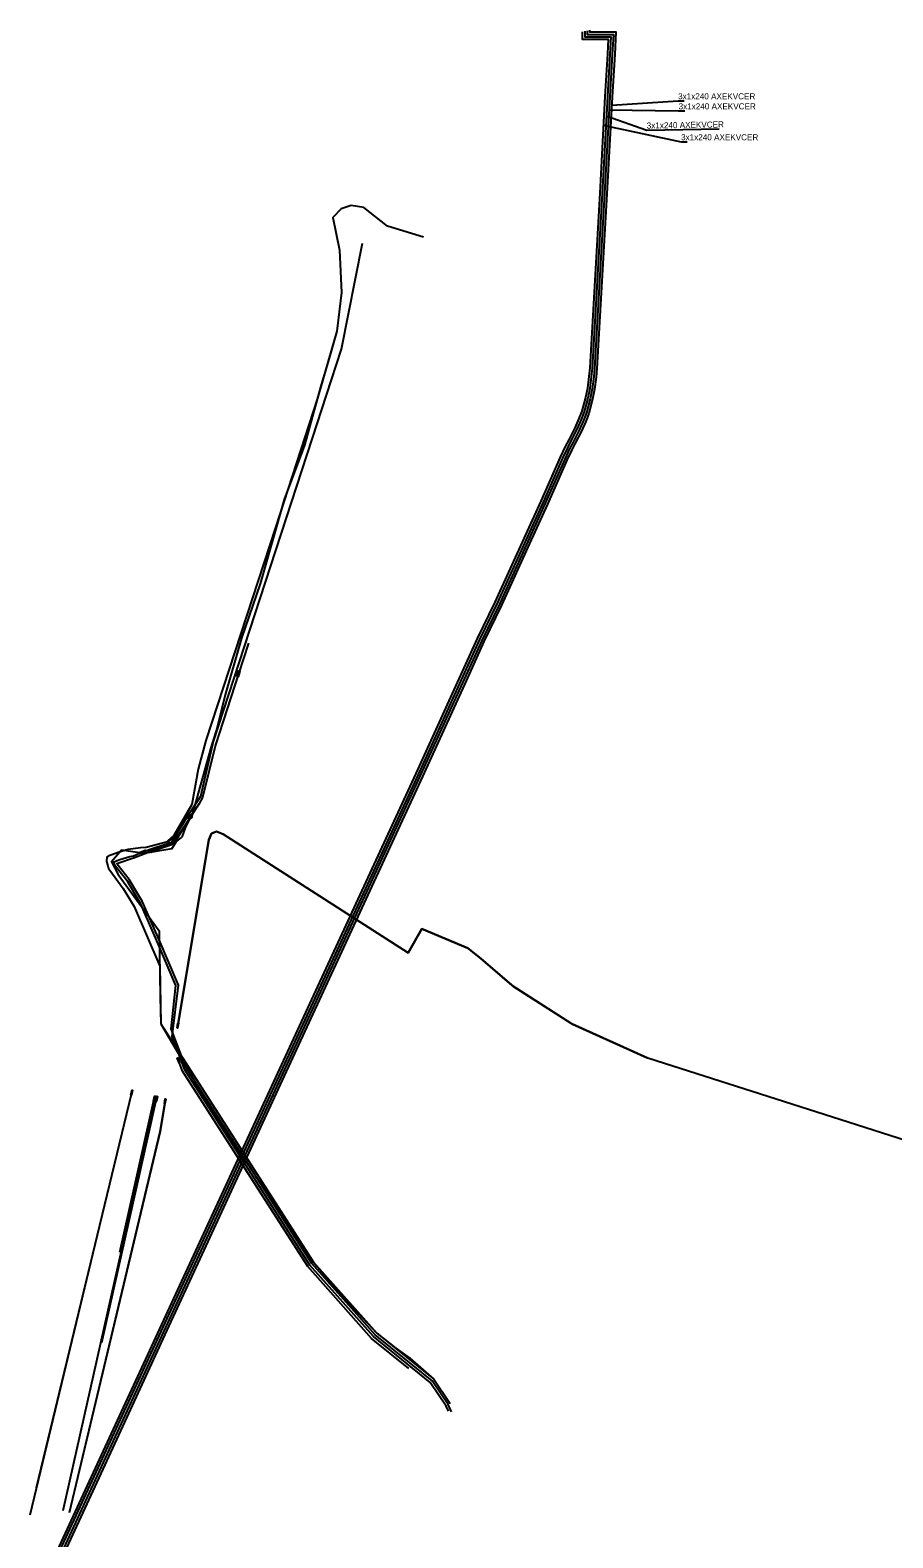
# Model space of a CAD drawing. Extents: x -739895 to -737975, y -1046419 to -1045728.
# Drawn here: x -739198.8 to -739056.8, y -1046188.1 to -1045939.9 of the extents above; entities that cross this region are included whole.
import ezdxf

# ---------------------------------------------------------------- set-up
doc = ezdxf.new("R2010")
doc.units = 0
for name, color, linetype in [('TRASA_KABELU_VN_VYRAZENO', 7, 'Continuous'), ('VN_KABEL_TUNEL_PROVOZ', 7, 'Continuous'), ('VN_KABELOVE_VEDENI_VYRAZENO', 7, 'Continuous'), ('VN_POPIS_USEKU', 7, 'Continuous'), ('VN_SPOJKA_KONCOVKA', 7, 'Continuous')]:
    doc.layers.add(name, color=color, linetype=linetype)

msp = doc.modelspace()

# ---------------------------------------------------------------- linework, layer by layer
at = {"layer": 'TRASA_KABELU_VN_VYRAZENO'}
msp.add_line((-739178.21, -1046115.97), (-739193.43, -1046183.61), dxfattribs=at)
for points in [[(-739148.32, -1045989.43), (-739149.62, -1045994.05), (-739150.99, -1045998.68), (-739153.66, -1046008.21), (-739156.99, -1046017.12), (-739160.95, -1046031.02), (-739164.01, -1046039.99), (-739166.72, -1046049.28), (-739168.02, -1046054.67), (-739169.05, -1046058.01), (-739172.05, -1046068.83), (-739173.23, -1046071.03), (-739173.85, -1046072.72)], [(-739179.85, -1046075.35), (-739178.93, -1046075.07), (-739176.29, -1046074.22), (-739175.36, -1046073.87), (-739174.34, -1046072.48), (-739172.35, -1046069.32), (-739172.05, -1046068.83)], [(-738876.38, -1046179.23), (-739024.54, -1046132.29), (-739066.73, -1046118.79), (-739097.09, -1046109.08), (-739109.65, -1046103.44), (-739119.45, -1046097.15), (-739124.59, -1046092.72), (-739126.74, -1046090.97), (-739134.31, -1046087.79), (-739136.59, -1046091.75), (-739167.03, -1046072.24), (-739168.14, -1046071.79), (-739168.96, -1046072.13), (-739169.37, -1046073.14), (-739174.49, -1046103.7)], [(-739175.5, -1046074.65), (-739174.74, -1046073.5), (-739173.85, -1046072.72)], [(-739175.5, -1046074.65), (-739180.04, -1046075.39), (-739183.77, -1046074.88), (-739185.43, -1046076.8), (-739184.29, -1046078.86), (-739177.54, -1046088.16), (-739177.39, -1046099.03), (-739177.26, -1046103.47), (-739174.03, -1046108.96)], [(-739174.03, -1046108.96), (-739169.11, -1046117.32), (-739152.13, -1046142.68), (-739146.27, -1046149.48), (-739141.75, -1046154.34), (-739138.61, -1046156.83), (-739136.28, -1046158.45), (-739132.33, -1046161.95)], [(-739198.8, -1046184.27), (-739187.7, -1046138.17), (-739182.07, -1046114.82)], [(-739192.34, -1046183.86), (-739177.42, -1046121.18), (-739176.59, -1046116.25)]]:
    msp.add_lwpolyline(points, dxfattribs=at)
at = {"layer": 'VN_KABEL_TUNEL_PROVOZ'}
for points in [[(-739107.92, -1045940.16), (-739107.91, -1045941.39), (-739103.63, -1045941.39), (-739103.76, -1045943.81), (-739104.18, -1045950.79), (-739105.04, -1045966.74), (-739106.69, -1045995.5), (-739106.82, -1045996.89), (-739107.05, -1045998.81), (-739107.38, -1046000.36), (-739107.99, -1046002.61), (-739108.45, -1046003.83), (-739109.14, -1046005.37), (-739110.14, -1046007.32), (-739110.71, -1046008.44), (-739111.53, -1046010.16), (-739114.74, -1046017.44), (-739122.29, -1046034.03), (-739125.19, -1046040.01), (-739135.31, -1046062.26), (-739198.32, -1046198.69)], [(-739107.51, -1045940.07), (-739107.51, -1045940.99), (-739103.21, -1045940.99), (-739103.36, -1045943.84), (-739103.78, -1045950.82), (-739104.65, -1045966.76), (-739106.29, -1045995.53), (-739106.42, -1045996.93), (-739106.66, -1045998.88), (-739106.99, -1046000.45), (-739107.61, -1046002.73), (-739108.08, -1046003.98), (-739108.78, -1046005.55), (-739109.79, -1046007.51), (-739110.35, -1046008.62), (-739111.16, -1046010.32), (-739114.37, -1046017.6), (-739121.92, -1046034.2), (-739124.82, -1046040.18), (-739134.94, -1046062.43), (-739197.96, -1046198.87)], [(-739107.11, -1045939.98), (-739107.11, -1045940.59), (-739102.79, -1045940.59), (-739102.96, -1045943.86), (-739103.38, -1045950.84), (-739104.24, -1045966.79), (-739105.89, -1045995.56), (-739106.03, -1045996.97), (-739106.26, -1045998.95), (-739106.6, -1046000.55), (-739107.23, -1046002.86), (-739107.71, -1046004.14), (-739108.42, -1046005.72), (-739109.43, -1046007.69), (-739110, -1046008.79), (-739110.8, -1046010.49), (-739114.01, -1046017.77), (-739121.56, -1046034.37), (-739124.46, -1046040.35), (-739134.58, -1046062.59), (-739197.61, -1046199.05)], [(-739106.71, -1045939.89), (-739106.71, -1045940.19), (-739102.36, -1045940.19), (-739102.56, -1045943.88), (-739102.98, -1045950.86), (-739103.85, -1045966.81), (-739105.49, -1045995.59), (-739105.63, -1045997.02), (-739105.87, -1045999.01), (-739106.21, -1046000.64), (-739106.85, -1046002.98), (-739107.34, -1046004.29), (-739108.06, -1046005.89), (-739109.07, -1046007.87), (-739109.64, -1046008.97), (-739110.44, -1046010.66), (-739113.64, -1046017.93), (-739116.58, -1046024.4), (-739121.2, -1046034.54), (-739124.1, -1046040.52), (-739127.03, -1046046.97), (-739134.21, -1046062.76), (-739139.84, -1046074.95), (-739143.87, -1046083.66), (-739150.56, -1046098.15), (-739157.62, -1046113.44), (-739162.78, -1046124.6), (-739170.22, -1046140.72), (-739176.62, -1046154.56), (-739182.96, -1046168.29), (-739189.49, -1046182.43), (-739195.85, -1046196.21)]]:
    msp.add_lwpolyline(points, dxfattribs=at)
at = {"layer": 'VN_KABELOVE_VEDENI_VYRAZENO'}
for p, q in [((-739162.84, -1046040.77), (-739164.52, -1046045.83)), ((-739186.98, -1046155.87), (-739177.98, -1046115.81)), ((-739184.06, -1046141.03), (-739178.38, -1046115.78))]:
    msp.add_line(p, q, dxfattribs=at)
for points in [[(-739134.05, -1045973.96), (-739139.96, -1045972.13), (-739143.84, -1045969.11), (-739145.95, -1045968.78), (-739147.6, -1045969.32), (-739148.98, -1045970.73), (-739147.9, -1045976.09), (-739147.55, -1045983.05), (-739148.32, -1045989.43), (-739151.49, -1046000.47), (-739158.41, -1046021.78), (-739169.89, -1046056.8), (-739171.13, -1046061.51), (-739172.17, -1046067.37), (-739173.99, -1046070.5), (-739175.33, -1046072.71), (-739175.79, -1046073.14)], [(-739180.29, -1046075.16), (-739178.24, -1046074.45), (-739175.49, -1046073.56), (-739172.71, -1046069.04), (-739170.68, -1046065.98), (-739168.74, -1046057.42), (-739168.68, -1046057.16), (-739152.34, -1046007.07), (-739150.02, -1046000), (-739147.53, -1045992.41), (-739144.07, -1045974.97)], [(-739164.52, -1046045.83), (-739168.3, -1046057.53), (-739170.42, -1046066.21), (-739171.03, -1046067.27), (-739172.39, -1046069.37)], [(-739172.39, -1046069.37), (-739173.38, -1046070.93), (-739173.97, -1046071.87), (-739174.79, -1046073.05)], [(-739174.49, -1046103.7), (-739169.37, -1046073.14), (-739168.96, -1046072.13), (-739168.14, -1046071.79), (-739167.03, -1046072.24), (-739136.59, -1046091.75), (-739134.31, -1046087.79), (-739126.74, -1046090.97), (-739124.59, -1046092.72), (-739119.58, -1046097.05), (-739119.32, -1046097.24), (-739109.79, -1046103.35), (-739109.5, -1046103.5), (-739097.2, -1046109.03), (-739096.96, -1046109.12), (-739086.49, -1046112.47)], [(-739175.79, -1046073.14), (-739176.21, -1046073.48), (-739179.69, -1046074.41), (-739180.61, -1046074.5), (-739182.67, -1046074.73), (-739184.33, -1046075.22), (-739185.97, -1046075.85), (-739186.19, -1046076.02), (-739186.25, -1046076.72), (-739186.01, -1046077.42), (-739185.92, -1046077.9), (-739185.7, -1046078.16), (-739183.47, -1046081.17), (-739181.69, -1046084.11), (-739177.46, -1046093.98), (-739177.26, -1046103.47), (-739152.13, -1046142.68), (-739141.75, -1046154.34), (-739132.33, -1046161.95), (-739129.64, -1046165.93)], [(-739174.79, -1046073.05), (-739175.36, -1046073.88), (-739176.24, -1046074.16), (-739178.92, -1046075.02)], [(-739129.45, -1046167.31), (-739130, -1046166.1), (-739132.63, -1046162.22), (-739142.02, -1046154.64), (-739152.45, -1046142.92), (-739173.18, -1046110.58), (-739175.61, -1046104.27), (-739174.8, -1046097.16), (-739177.93, -1046089.79), (-739180.55, -1046083.77), (-739182.72, -1046080.1), (-739184.58, -1046077.74), (-739184.85, -1046077.35), (-739185.01, -1046076.8), (-739184.01, -1046076.41), (-739182.39, -1046075.89), (-739181.79, -1046075.77), (-739180.29, -1046075.16)], [(-739129.94, -1046167.2), (-739130.3, -1046166.38), (-739132.93, -1046162.49), (-739142.3, -1046154.93), (-739152.77, -1046143.17), (-739173.36, -1046111.04), (-739175.43, -1046105.54), (-739174.39, -1046097.07), (-739177.57, -1046089.61), (-739180.36, -1046083.28), (-739180.98, -1046082.25), (-739182.51, -1046079.7), (-739184.31, -1046077.39), (-739184.52, -1046077.05), (-739181.64, -1046076.09), (-739178.92, -1046075.02)], [(-739136.47, -1046160.15), (-739142.58, -1046155.22), (-739153.09, -1046143.41), (-739173.72, -1046111.23), (-739174.37, -1046109.5)], [(-739197.74, -1046179.79), (-739187.7, -1046138.17), (-739182.07, -1046114.82)], [(-739176.59, -1046116.25), (-739177.42, -1046121.18), (-739191.21, -1046179.11)]]:
    msp.add_lwpolyline(points, dxfattribs=at)
at = {"layer": 'VN_POPIS_USEKU'}
for points in [[(-739103.03, -1045952.26), (-739092.13, -1045951.53), (-739091.13, -1045951.53)], [(-739103.95, -1045953.99), (-739097.29, -1045956.35), (-739085.37, -1045956.16)], [(-739103.54, -1045952.99), (-739092.05, -1045953.18), (-739091.05, -1045953.18)], [(-739104.46, -1045955.52), (-739091.64, -1045958.27), (-739090.64, -1045958.27)]]:
    msp.add_lwpolyline(points, dxfattribs=at)
at = {"layer": 'VN_SPOJKA_KONCOVKA'}
for points in [[(-739164.76, -1046046.28), (-739164.45, -1046045.32), (-739164.27, -1046045.38), (-739164.58, -1046046.34)], [(-739175.35, -1046072.87), (-739176.1, -1046073.55), (-739176.22, -1046073.41), (-739175.47, -1046072.73)], [(-739174.43, -1046072.68), (-739174.99, -1046073.52), (-739175.15, -1046073.42), (-739174.58, -1046072.58)], [(-739180.8, -1046075.25), (-739179.85, -1046074.89), (-739179.78, -1046075.06), (-739180.73, -1046075.43)], [(-739174.38, -1046103.32), (-739174.52, -1046104.14), (-739174.61, -1046104.13), (-739174.46, -1046103.31), (-739174.43, -1046103.31), (-739174.57, -1046104.08), (-739174.54, -1046104.08), (-739174.41, -1046103.32)], [(-739174.27, -1046109.88), (-739174.57, -1046109.1), (-739174.49, -1046109.07), (-739174.19, -1046109.85), (-739174.21, -1046109.86), (-739174.49, -1046109.13), (-739174.52, -1046109.14), (-739174.24, -1046109.87)], [(-739182.2, -1046115.19), (-739182.01, -1046114.37), (-739181.93, -1046114.39), (-739182.12, -1046115.21), (-739182.15, -1046115.2), (-739181.97, -1046114.44), (-739182, -1046114.43), (-739182.17, -1046115.19)], [(-739178.51, -1046116.15), (-739178.32, -1046115.33), (-739178.24, -1046115.35), (-739178.43, -1046116.17), (-739178.45, -1046116.16), (-739178.28, -1046115.4), (-739178.3, -1046115.4), (-739178.48, -1046116.16)], [(-739178.11, -1046116.18), (-739177.92, -1046115.37), (-739177.84, -1046115.39), (-739178.02, -1046116.2), (-739178.05, -1046116.2), (-739177.88, -1046115.44), (-739177.9, -1046115.43), (-739178.08, -1046116.19)], [(-739176.7, -1046116.63), (-739176.55, -1046115.81), (-739176.47, -1046115.82), (-739176.62, -1046116.64), (-739176.64, -1046116.64), (-739176.51, -1046115.87), (-739176.54, -1046115.87), (-739176.67, -1046116.63)]]:
    msp.add_lwpolyline(points, close=True, dxfattribs=at)
for points in [[(-739172.65, -1046069.83), (-739172.6, -1046069.25), (-739172.13, -1046068.92), (-739172.18, -1046069.49), (-739172.65, -1046069.83)], [(-739179.42, -1046075.2), (-739179.01, -1046074.8), (-739178.43, -1046074.84), (-739178.84, -1046075.25), (-739179.42, -1046075.2)]]:
    msp.add_lwpolyline(points, dxfattribs=at)

# ---------------------------------------------------------------- texts
at = {"layer": 'VN_POPIS_USEKU'}
for p in [(-739092.13, -1045951.28), (-739092.05, -1045952.93), (-739091.64, -1045958.02)]:
    msp.add_text('3x1x240 AXEKVCER', height=1, dxfattribs=at).set_placement(p)
msp.add_text('3x1x240 AXEKVCER', height=1, rotation=0.9069, dxfattribs=at).set_placement((-739097.29, -1045956.1))

doc.saveas('drawing.dxf')
